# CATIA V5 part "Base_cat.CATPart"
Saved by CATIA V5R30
Part number: Base
Bounding box of the stored display mesh (mm): x -24 to 24, y 0 to 90, z 0 to 54
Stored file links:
  D:\PROJECTS\CATIA V56R 2020\Resources\c14\c14tut2\c14tut2.CATParts\Base_cat.CATPart
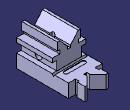
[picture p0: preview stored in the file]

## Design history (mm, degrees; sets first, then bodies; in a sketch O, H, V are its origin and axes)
Body1 (main body)
  Sketch1 on xy-plane, origin (0, 0, 0), H (1, 0, 0), V (0, 1, 0)
    line L1 (-24, 0) -> (24, 0)
    point P2 (24, 0)
    construction line L2 (-23.876, 50.8) -> (23.876, 50.8)
    point P3 (-23.876, 50.8)
    point P4 (23.876, 50.8)
    line L3 (24, 0) -> (24, 74)
    point P5 (24, 74)
    line L4 (24, 74) -> (14, 74)
    point P6 (14, 74)
    line L5 (14, 74) -> (14, 79)
    point P7 (14, 79)
    line L6 (14, 79) -> (16.5, 79)
    point P8 (16.5, 79)
    line L7 (16.5, 79) -> (16.5, 90)
    point P9 (16.5, 90)
    line L8 (16.5, 90) -> (13.5, 90)
    point P10 (13.5, 90)
    line L9 (13.5, 90) -> (2, 78.5)
    point P11 (2, 78.5)
    line L10 (2, 78.5) -> (2, 74)
    point P12 (2, 74)
    line L11 (2, 74) -> (0, 74)
    point P13 (0, 74)
    point P14 (0, 74)
    point P15 (-2, 74)
    line L12 (-2, 74) -> (0, 74)
    point P16 (-2, 78.5)
    line L13 (-2, 78.5) -> (-2, 74)
    point P17 (-13.5, 90)
    line L14 (-13.5, 90) -> (-2, 78.5)
    point P18 (-16.5, 90)
    line L15 (-16.5, 90) -> (-13.5, 90)
    point P19 (-16.5, 79)
    line L16 (-16.5, 79) -> (-16.5, 90)
    point P20 (-14, 79)
    line L17 (-14, 79) -> (-16.5, 79)
    point P21 (-14, 74)
    line L18 (-14, 74) -> (-14, 79)
    point P22 (-24, 74)
    line L19 (-24, 74) -> (-14, 74)
    point P23 (-23.876, 50.8)
    point P24 (23.876, 50.8)
    construction line L20 (23.876, 50.8) -> (-23.876, 50.8)
    point P25 (-24, 0)
    line L21 (-24, 0) -> (-24, 74)
    distance P2 V = 24
    distance L13 L10 = 4
    distance L16 L7 = 33
    distance L5 L3 = 10
    length L18 = 5
    angle L14 L9 = 90
    distance L4 L8 = 16
    distance P17 P10 = 27
    distance L1 L8 = 90
    length L1 = 48
    horizontal: L1 H, L2 H, L4 H, L6 H, L8 H, L11 H
    coincidence: H L1, P13 V, P13 P14, L12 L4
    vertical: L3 V, L5 V, L7 V, L10 V
    symmetry: P13 P14 V, P12 P15 V, L11 L12 V, P11 P16 V, L10 L13 V, P10 P17 V, L9 L14 V, P9 P18 V, L8 L15 V, P8 P19 V, L7 L16 V, P7 P20 V, L6 L17 V, P6 P21 V, L5 L18 V, P5 P22 V, L4 L19 V, P4 P23 V, P3 P24 V, L2 L20 V, P2 P25 V, L3 L21 V
  Pad1: profile Sketch1, direction (0, 0, 1), length 19
  Sketch2 on face of Pad1, origin (0, 0, 0), H (1, 0, 0), V (0, 0, 1)
    line L1 (17.5, 19) -> (17.5, 32)
    point P1 (17.5, 19)
    point P2 (17.5, 32)
    line L2 (17.5, 32) -> (24, 32)
    point P3 (24, 32)
    line L3 (24, 32) -> (24, 38)
    point P4 (24, 38)
    line L4 (24, 38) -> (13.5, 38)
    point P5 (13.5, 38)
    line L5 (13.5, 38) -> (13.5, 43)
    point P6 (13.5, 43)
    line L6 (13.5, 43) -> (16.5, 43)
    point P7 (16.5, 43)
    line L7 (16.5, 43) -> (16.5, 54)
    point P8 (16.5, 54)
    reference projected line E1 (24, 19) -> (-24, 19) from edge of Pad1
    reference projected line E2 (24, 0) -> (24, 19) from edge of Pad1
    line L8 (16.5, 54) -> (12.9083, 54)
    point P9 (12.9083, 54)
    point P10 (2, 41)
    line L9 (2, 41) -> (2, 38)
    point P11 (2, 38)
    line L10 (2, 38) -> (0, 38)
    point P12 (0, 38)
    line L11 (2, 41) -> (12.9083, 54)
    point P13 (-12.9083, 54)
    point P14 (-2, 41)
    line L12 (-2, 41) -> (-12.9083, 54)
    point P15 (0, 38)
    point P16 (-2, 38)
    line L13 (-2, 38) -> (0, 38)
    line L14 (-2, 41) -> (-2, 38)
    point P17 (-16.5, 54)
    line L15 (-16.5, 54) -> (-12.9083, 54)
    point P18 (-16.5, 43)
    line L16 (-16.5, 43) -> (-16.5, 54)
    point P19 (-13.5, 43)
    line L17 (-13.5, 43) -> (-16.5, 43)
    point P20 (-13.5, 38)
    line L18 (-13.5, 38) -> (-13.5, 43)
    point P21 (-24, 38)
    line L19 (-24, 38) -> (-13.5, 38)
    point P22 (-24, 32)
    line L20 (-24, 32) -> (-24, 38)
    point P23 (-17.5, 32)
    line L21 (-17.5, 32) -> (-24, 32)
    point P24 (-17.5, 19)
    line L22 (-17.5, 19) -> (-17.5, 32)
    line L23 (-17.5, 19) -> (17.5, 19)
    distance L2 H = 32
    distance L4 H = 38
    distance L6 H = 43
    distance L8 H = 54
    distance L9 V = 2
    length L9 = 3
    distance L22 L1 = 35
    distance L7 L16 = 33
    angle L12 L11 = 80
    distance L18 L5 = 27
    vertical: L1 V, L3 V, L5 V, L7 V, L9 V
    horizontal: L2 H, L4 H, L6 H, L8 H, L10 H, L23 H
    coincidence: P1 E1, L3 E2, P11 L4, P12 V, P12 P15
    symmetry: P9 P13 V, P10 P14 V, L11 L12 V, P12 P15 V, P11 P16 V, L10 L13 V, L9 L14 V, P8 P17 V, L8 L15 V, P7 P18 V, L7 L16 V, P6 P19 V, L6 L17 V, P5 P20 V, L5 L18 V, P4 P21 V, L4 L19 V, P3 P22 V, L3 L20 V, P2 P23 V, L2 L21 V, P1 P24 V, L1 L22 V
  Pad2: profile Sketch2, direction (0, 1, 0), length 50.8
  Sketch3 on face of Pad1, origin (4.0235, 27.8102, 0), H (1, 0, 0), V (0, -1, 0)
    point P1 (-4.0235, 2.8102)
    reference intersected line E1 through (-4.0235, 0) direction (0, 1) from yz-plane
    reference projected line E2 (-6.0235, 27.8102) -> (-16.9318, 27.8102) from edge [face of Pad2 from Sketch2.L12 | start face of Pad2]
    distance P1 E2 = 25
    coincidence: E1 P1
  Hole1: placed by Sketch3, at (0, 25, 0) direction (0, 0, 1), diameter 8, depth 54.102
  Sketch4 on face of Pad2, origin (17.5, 12.3932, 23.5222), H (0, 1, 0), V (0, 0, 1)
    point P1 (12.6068, 1.4778)
    reference projected line E1 (-12.3932, 8.4778) -> (-12.3932, -4.5222) from edge of Pad2
    reference projected line E2 (-12.3932, -23.5222) -> (61.6068, -23.5222) from edge of Pad1
    distance E1 P1 = 25
    distance E2 P1 = 25
  Hole2: placed by Sketch4, at (17.5, 25, 25) direction (-1, 0, 0), diameter 10, depth 54.102
  Sketch5 on face of Pad1, origin (0, 0, 19), H (1, 0, 0), V (0, 1, 0)
    construction line L1 (-24, 59) -> (24, 59)
    point P1 (-24, 59)
    point P2 (24, 59)
    construction line L2 (-12.5, 59) -> (12.5, 59)
    point P3 (-12.5, 59)
    point P4 (12.5, 59)
    line L3 (-12.5, 62) -> (12.5, 62)
    line L4 (12.5, 56) -> (-12.5, 56)
    arc A1 centre (12.5, 59) radius 3 from (12.5, 62) to (12.5, 56) cw
    arc A2 centre (-12.5, 59) radius 3 from (-12.5, 56) to (-12.5, 62) cw
    reference projected line E1 (24, 74) -> (24, 0) from edge of Pad1
    reference projected line E2 (-24, 74) -> (-24, 0) from edge of Pad1
    reference projected line E3 (24, 74) -> (14, 74) from edge [face of Pad1 from Sketch1.L4 | end face of Pad1]
    radius A1 = 3
    distance L2 E3 = 15
    length L2 = 25
    distance V P4 = 12.5
    horizontal: L1 H, L2 H
    coincidence: P3 L1, P2 E1, P1 E2
    tangency: A1 L3, A2 L3, A1 L4, A2 L4
    parallelism: L2 L3
  Pocket1: profile Sketch5, direction (0, 0, -1), length 1
  Sketch6 on face of Pad1, origin (24, 0, 0), H (0, 1, 0), V (0, 0, 1)
    point P1 (50.8, 19)
    line L1 (50.8, 19) -> (52.5321, 16)
    point P2 (52.5321, 16)
    line L2 (52.5321, 16) -> (54.2641, 19)
    line L3 (54.2641, 19) -> (50.8, 19)
    reference projected line E1 (74, 19) -> (0, 19) from edge of Pad1
    construction line L4 (52.5321, 16) -> (52.5321, 29.45)
    reference projected line E2 (50.8, 19) -> (50.8, 32) from edge [end face of Pad2 | face of Pad2 from Sketch2.L1]
    angle L1 L2 = 60
    distance P2 L3 = 3
    angle L4 L2 = 30
    horizontal: L3 H
    coincidence: L3 E1, P1 E2
    vertical: L4 V
  Pocket2: profile Sketch6, direction (-1, 0, 0), through (limit type 6)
